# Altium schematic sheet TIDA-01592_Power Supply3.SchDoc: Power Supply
size 431 x 279 mm; Date: Not shown in title block; ApprovedBy: Not shown in title block; CheckedBy: Not shown in title block; Author: Not shown in title block; CompanyName: Not shown in title block; DrawnBy: Abhishek Vishwa; Engineer: Abhishek Vishwa; Organization: Not shown in title block; Address1: Not shown in title block; Address2: Not shown in title block; Address3: Not shown in title block; Address4: Not shown in title block; DocumentNumber: 1; Revision: Use project parameter SCH_Rev; SheetNumber: 4; SheetTotal: 5; PageSetup: Record=PageOptions¦CenterHorizontal=True¦CenterVertical=True¦PrintScale=1.00¦XCorrection=1.00¦YCorrection=1.00¦PrintKind=0¦BorderSize=5000000¦LeftOffset=0¦BottomOffset=0¦Orientation=2¦PaperLength=1000¦PaperWidth=1000¦Scale=100¦PaperSource=15¦PrintQuality=600¦MediaType=1¦DitherType=10¦PaperKind=Letter¦PrintScaleMode=1
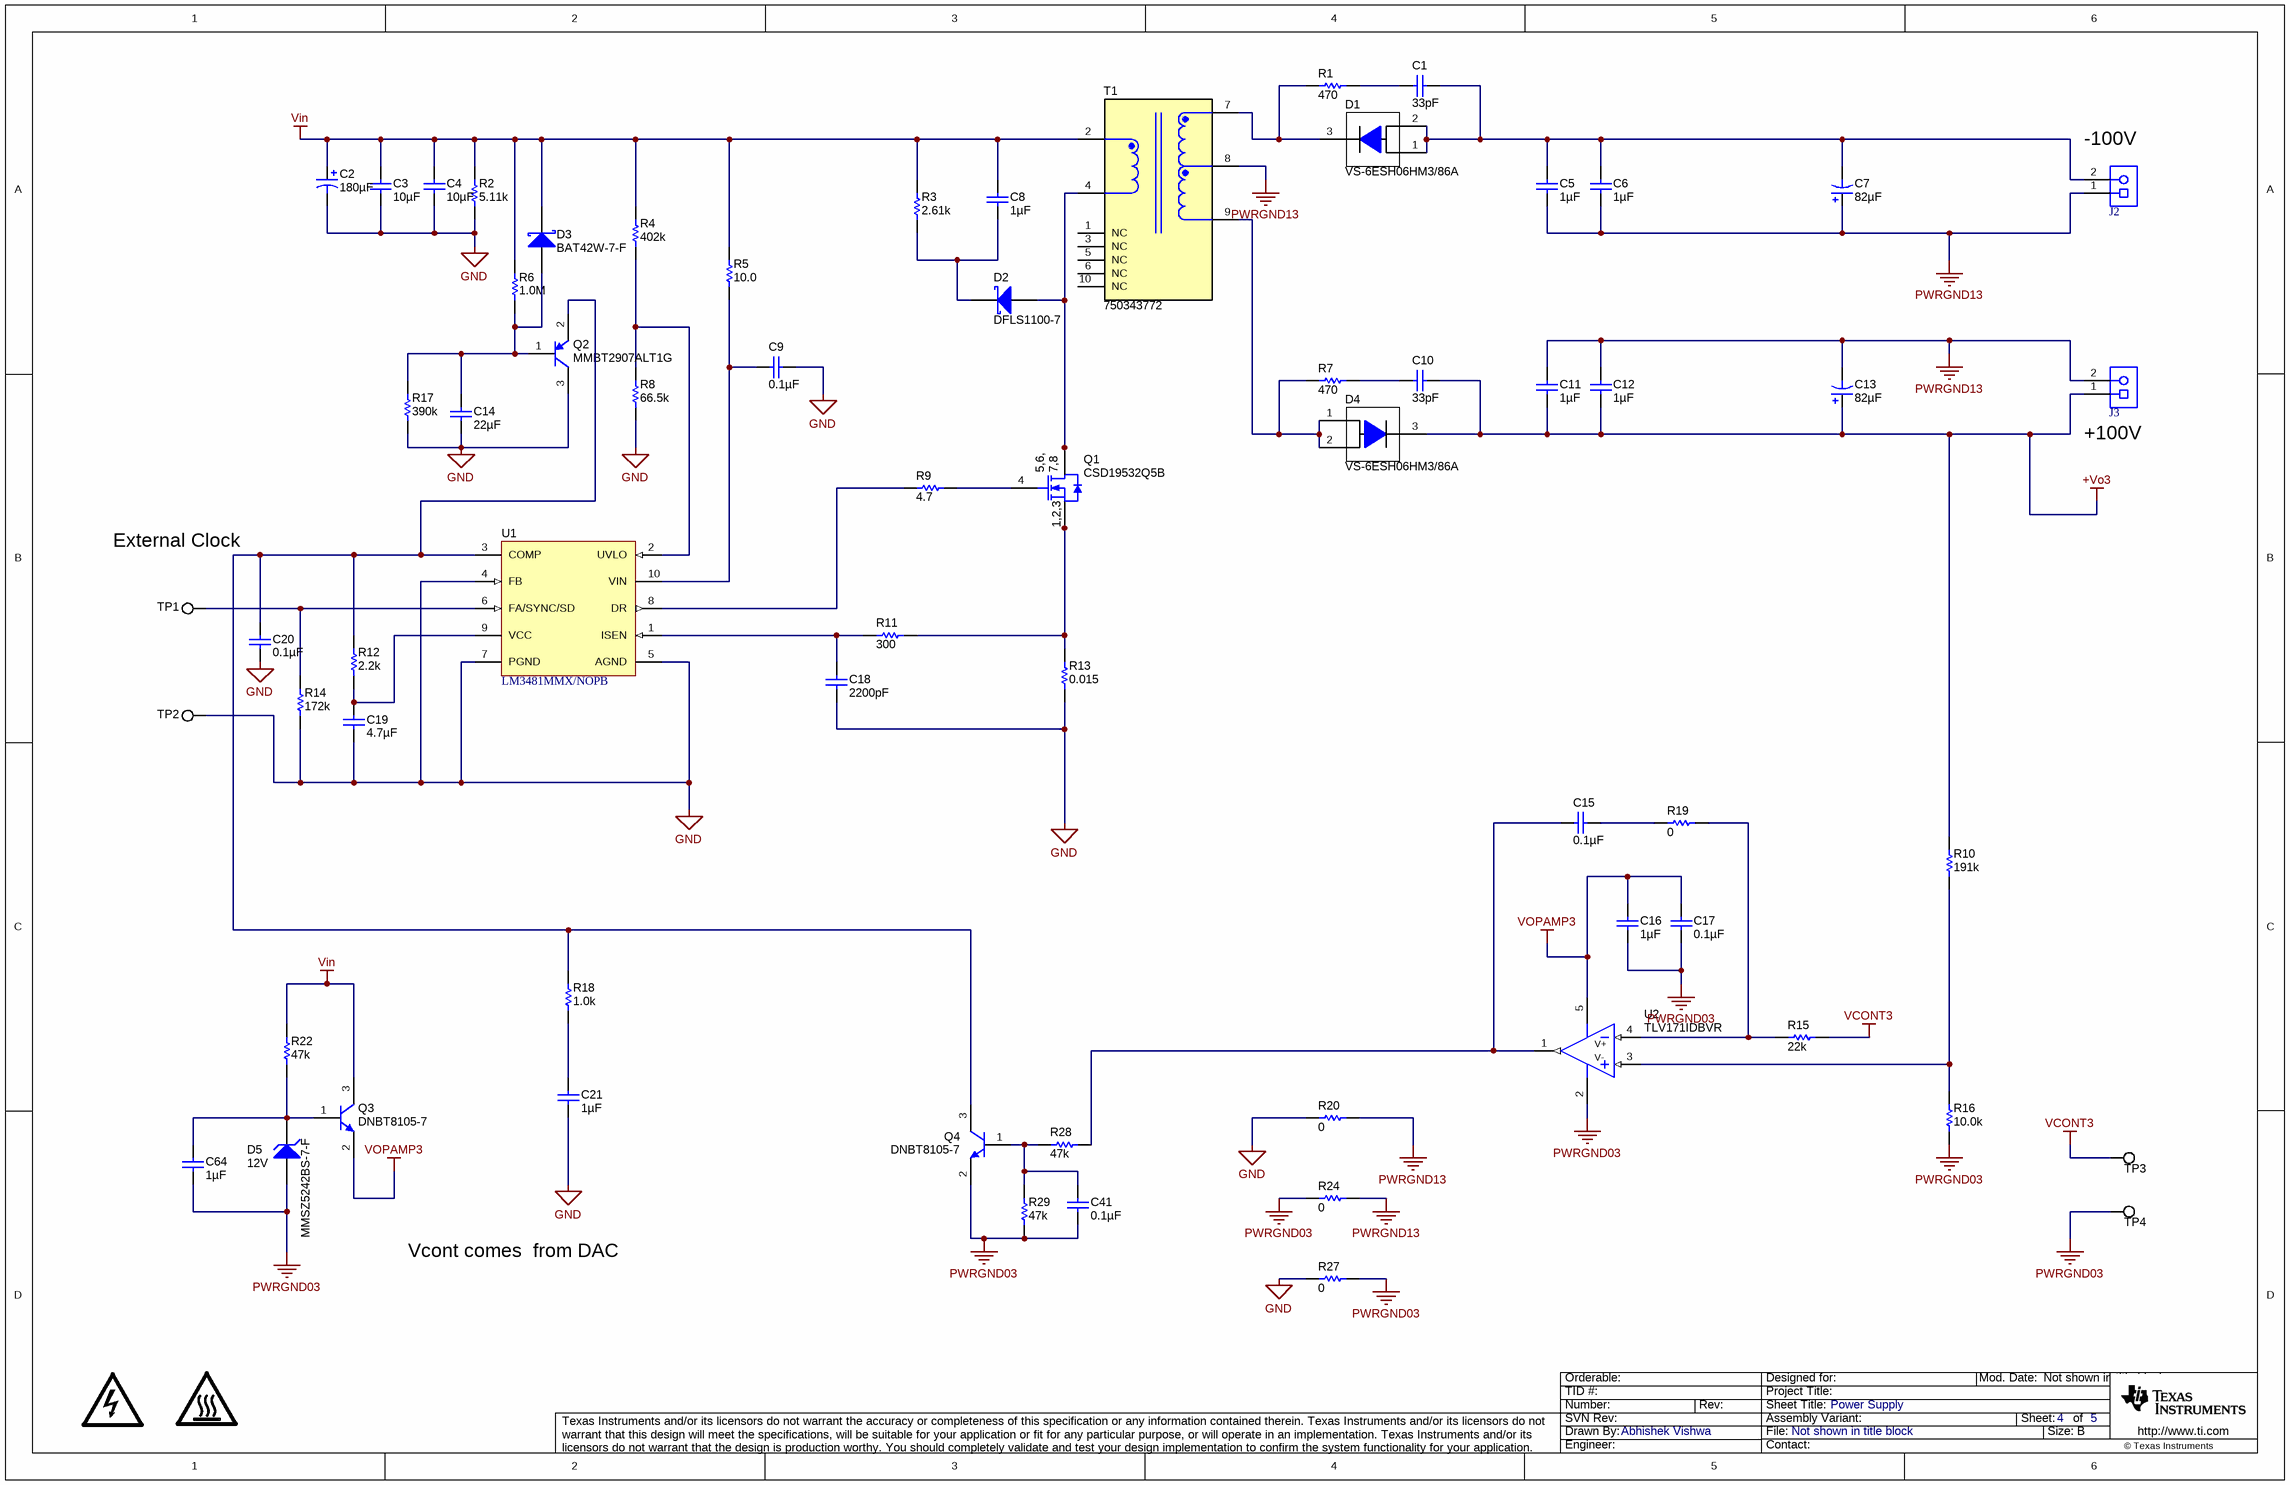
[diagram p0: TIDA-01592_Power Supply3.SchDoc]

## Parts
C1  ValueDisplayed: 33pF  [1206]  (hidden comment: 12067A330JAT2A)
C2  ValueDisplayed: 180µF  [FC_630x1120]  (hidden comment: 35TXW180MEFC6.3X25)
C3  ValueDisplayed: 10µF  [1206_180]  (hidden comment: GRM31CR61H106KA12L)
C4  ValueDisplayed: 10µF  [1206_180]  (hidden comment: GRM31CR61H106KA12L)
C5  ValueDisplayed: 1µF  [1812_180]  (hidden comment: C4532X7T2E105M250KE)
C6  ValueDisplayed: 1µF  [1812_180]  (hidden comment: C4532X7T2E105M250KE)
C7  ValueDisplayed: 82µF  [NHG_1000x2000]  (hidden comment: UCY2C820MPD9)
C8  ValueDisplayed: 1µF  [1206_180]  (hidden comment: GRM31CR72A105KA01L)
C9  ValueDisplayed: 0.1µF  [0603]  (hidden comment: GRM188R71H104KA93D)
C10  ValueDisplayed: 33pF  [1206]  (hidden comment: 12067A330JAT2A)
C11  ValueDisplayed: 1µF  [1812_180]  (hidden comment: C4532X7T2E105M250KE)
C12  ValueDisplayed: 1µF  [1812_180]  (hidden comment: C4532X7T2E105M250KE)
C13  ValueDisplayed: 82µF  [NHG_1000x2000]  (hidden comment: UCY2C820MPD9)
C14  ValueDisplayed: 22µF  [0805_HV1]  (hidden comment: C2012X5R1V226M125AC)
C15  ValueDisplayed: 0.1µF  [0603]  (hidden comment: GRM188R71H104KA93D)
C16  ValueDisplayed: 1µF  [0603]  (hidden comment: UMK107AB7105KA-T)
C17  ValueDisplayed: 0.1µF  [0603]  (hidden comment: GRM188R71H104KA93D)
C18  ValueDisplayed: 2200pF  [0402]  (hidden comment: GRM155R61H222KA01D)
C19  ValueDisplayed: 4.7µF  [0603]  (hidden comment: 0603ZD475KAT2A)
C20  ValueDisplayed: 0.1µF  [0603]  (hidden comment: GRM188R71H104KA93D)
C21  ValueDisplayed: 1µF  [0603]  (hidden comment: C0603C105K3RACTU)
C41  ValueDisplayed: 0.1µF  [0603]  (hidden comment: GRM188R71H104KA93D)
C64  ValueDisplayed: 1µF  [0603]  (hidden comment: C0603C105K3RACTU)
D1  VS-6ESH06HM3/86A  [TO-277A]
D2  DFLS1100-7  [PowerDI123]
D3  BAT42W-7-F  [SOD-123]
D4  VS-6ESH06HM3/86A  [TO-277A]
D5  MMSZ5242BS-7-F  value 12V  [SOD-323]
J2  1727010  [PhoenixConact_1727010]  (value not drawn)
J3  1727010  [PhoenixConact_1727010]  (value not drawn)
LOGO2  CAUTION HOT SURFACE  [IEC_HotSurface_Small]  (value not drawn)  (graphical)
LOGO8  DANGER HIGH VOLTAGE  [IEC_HighVoltage_Small]  (value not drawn)  (graphical)
Q1  CSD19532Q5B  [DNK0008A]
Q2  MMBT2907ALT1G  [SOT-23]
Q3  DNBT8105-7  [SOT-23]
Q4  DNBT8105-7  [SOT-23]
R1  ValueDisplayed: 470  [1206]  (hidden comment: CRCW1206470RJNEA)
R2  ValueDisplayed: 5.11k  [TNPW0603]  (hidden comment: TNPW06035K11BEEA)
R3  ValueDisplayed: 2.61k  [2010]  (hidden comment: CRCW20102K61FKEF)
R4  ValueDisplayed: 402k  [0603]  (hidden comment: CRCW0603402KFKEA)
R5  R4: 10.0  [0603]  (hidden comment: CRCW060310R0FKEAHP)
R6  ValueDisplayed: 1.0M  [0603]  (hidden comment: CRCW06031M00JNEA)
R7  ValueDisplayed: 470  [1206]  (hidden comment: CRCW1206470RJNEA)
R8  ValueDisplayed: 66.5k  [0603]  (hidden comment: CRCW060366K5FKEA)
R9  ValueDisplayed: 4.7  [0603]  (hidden comment: CRCW06034R70JNEA)
R10  ValueDisplayed: 191k  [0603]  (hidden comment: CRCW0603191KFKEA)
R11  ValueDisplayed: 300  [0603]  (hidden comment: CRCW0603300RJNEA)
R12  ValueDisplayed: 2.2k  [0603]  (hidden comment: ERJ-3GEYJ222V)
R13  ValueDisplayed: 0.015  [2010]  (hidden comment: WSL2010R0150FEA18)
R14  ValueDisplayed: 172k  [0603]  (hidden comment: RT0603DRE07172KL)
R15  ValueDisplayed: 22k  [0603]  (hidden comment: CRCW060322K0JNEA)
R16  ValueDisplayed: 10.0k  [0603]  (hidden comment: CRCW060310K0FKEA)
R17  ValueDisplayed: 390k  [0603]  (hidden comment: CRCW0603390KJNEA)
R18  ValueDisplayed: 1.0k  [0603]  (hidden comment: CRCW06031K00JNEA)
R19  ValueDisplayed: 0  [0402]  (hidden comment: CRCW04020000Z0ED)
R20  ValueDisplayed: 0  [2010L]  (hidden comment: CRCW20100000Z0EF)
R22  ValueDisplayed: 47k  [1206]  (hidden comment: CRCW120647K0JNEA)
R24  ValueDisplayed: 0  [2010L]  (hidden comment: CRCW20100000Z0EF)
R27  ValueDisplayed: 0  [2010L]  (hidden comment: CRCW20100000Z0EF)
R28  ValueDisplayed: 47k  [0603]  (hidden comment: RC0603JR-0747KL)
R29  ValueDisplayed: 47k  [0603]  (hidden comment: RC0603JR-0747KL)
T1  750343772  [Wurth_EE16_7_5_5278]
TP1  5002  [Keystone5002]  (value not drawn)
TP2  5002  [Keystone5002]  (value not drawn)
TP3  5002  [Keystone5002]  (value not drawn)
TP4  5002  [Keystone5002]  (value not drawn)
U1  LM3481MMX/NOPB  [MUB10A_N]
U2  TLV171IDBVR  [DBV0005A_N]

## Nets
+Vo3: C10.1 C11.2 C12.2 C13.1(+) D4.3(K) J3.1 R10.2
GND: C2.2(-) C3.2 C4.2 C9.1 C14.2 C18.2 C19.2 C20.1 C21.2 Q2.3(C) R2.1 R8.1 R13.1 R14.1 R17.1 R20.1 R27.1 TP2.1 U1.4(FB) U1.5(AGND) U1.7(PGND)
PWRGND03: C16.2 C17.2 C41.1 C64.2 D5.2(A) Q4.2(E) R16.2 R24.1 R27.2 R29.2 TP4.1 U2.2(V-)
PWRGND13: C5.2 C6.2 C7.1(+) C11.1 C12.1 C13.2(-) J2.1 J3.2 R20.2 R24.2 T1.8
VCONT3: R15.2 TP3.1
Vin: C2.1(+) C3.1 C4.1 C8.1 D3.1(K) Q3.3(C) R2.2 R3.2 R4.2 R5.1 R6.2 R22.2 T1.2
VOPAMP3: C16.1 C17.1 Q3.2(E) U2.5(V+)
NetC1_1: C1.1 C5.1 C6.1 C7.2(-) D1.1(A) D1.2(A) J2.2
NetC1_2: C1.2 R1.2
NetC8_2: C8.2 D2.1(K) R3.1
NetC9_2: C9.2 R5.2 U1.10(VIN)
NetC10_2: C10.2 R7.2
NetC14_1: C14.1 D3.2(A) Q2.1(B) R6.1 R17.2
NetC15_1: C15.1 R28.1 U2.1(OUT)
NetC15_2: C15.2 R19.1
NetC18_1: C18.1 R11.1 U1.1(ISEN)
NetC19_1: C19.1 R12.2 U1.9(VCC)
NetC20_2: C20.2 Q2.2(E) Q4.3(C) R12.1 R18.2 U1.3(COMP)
NetC21_1: C21.1 R18.1
NetC41_2: C41.2 Q4.1(B) R28.2 R29.1
NetC64_1: C64.1 D5.1(K) Q3.1(B) R22.1
NetD1_3: D1.3(K) R1.1 T1.7
NetD2_2: D2.2(A) Q1.5(D) Q1.6(D) Q1.7(D) Q1.8(D) Q1.9(D) T1.4
NetD4_1: D4.1(A) D4.2(A) R7.1 T1.9
NetQ1_1: Q1.1(S) Q1.2(S) Q1.3(S) R11.2 R13.2
NetQ1_4: Q1.4(G) R9.2
NetR4_1: R4.1 R8.2 U1.2(UVLO)
NetR9_1: R9.1 U1.8(DR)
NetR10_1: R10.1 R16.1 U2.3(IN+)
NetR14_2: R14.2 TP1.1 U1.6(FA/SYNC/SD)
NetR15_1: R15.1 R19.2 U2.4(IN-)

Not connected (* = marked no-connect by the designer): T1 1(NC) 3(NC) 5(NC) 6(NC) 10(NC)

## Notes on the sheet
- (near J2) -100V
- (near J3) +100V
- External Clock Synchronization
- Vcont comes  from DAC

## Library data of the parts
C1 C10 = 12067A330JAT2A: CAP, CERM, 33 pF, 500 V,+/- 5%, C0G/NP0, 1206; Manufacturer: AVX; Polarized: N; CompType: Capacitor; Value: 33pF; U/M: EA; Cap_F: 0.000000000033; Tolerance_%: 5; VDC_V: 500; Value2: 500V; TaMin_C: -55; TaMax_C: 125; SizeArea_mm2: 5.12; SizeAreaWB_mm2: 10.92; SizeX_mm: 3.2; SizeY_mm: 1.6; SizeZ_mm: 1.35; AEC Category: Q200; Green_Lifecycle: Not Set; Green_REACh: Incomplete
C2 = EEU-FC1V470: CAP, AL, 180 µF, 35 V, +/- 20%, TH; Manufacturer: Rubycon; Polarized: Y; CompType: Capacitor; Value: 180uF; U/M: EA; Cap_F: 0.000180; Tolerance_%: 20; VDC_V: 35; Value2: 35V; IRMS_A: 0.29; TaMin_C: -55; TaMax_C: 105; Cap_Case: 6.3x11.2mm; SizeAreaWB_mm2: 68.89; SizeArea_mm2: 39.69; SizeX_mm: 6.3; SizeZ_mm: 12.2; AEC Category: Q200; AEC Grade: 2
C3 C4 = GRM31CR61H106KA12L: CAP, CERM, 10 µF, 50 V,+/- 10%, X5R, 1206; Manufacturer: MuRata; Polarized: N; CompType: Capacitor; Value: 10uF; U/M: EA; Cap_F: 0.00001; Tolerance_%: 10; VDC_V: 50; Value2: 50V; TaMin_C: -55; TaMax_C: 85; Cap_Case: 1206; SizeArea_mm2: 5.12; SizeAreaWB_mm2: 10.92; SizeX_mm: 3.2; SizeY_mm: 1.6; SizeZ_mm: 1.8; AEC Category: Q200; Green_Lifecycle: Active; Green_REACh: Passed
C5 C6 C11 C12 = C4532X7R1H105K160KA: CAP, CERM, 1 µF, 250 V,+/- 20%, X7T, 1812; Manufacturer: TDK Corporation; Polarized: N; CompType: Capacitor; Value: 1uF; U/M: EA; Cap_F: 0.000001; Tolerance_%: 20; ESR_ohm: 0.007217; Value1: 0.007217 ohm; VDC_V: 50; Value2: 250V; IRMS_A: 2.85919; TaMin_C: -55; TaMax_C: 125; Cap_Case: 1812; SizeArea_mm2: 14.4; SizeAreaWB_mm2: 23.1; SizeX_mm: 4.5; SizeY_mm: 3.2; SizeZ_mm: 1.8; AEC Category: Q200
C7 C13 = ECA-2AHG101: CAP, AL, 82 µF, 160 V, +/- 20%, TH; Manufacturer: Nichicon; Polarized: Y; CompType: Capacitor; Value: 82uF; U/M: EA; Cap_F: 0.0001; Tolerance_%: 20; VDC_V: 160; Value2: 160V; IRMS_A: 0.265; TaMin_C: -55; TaMax_C: 105; Cap_Case: 10x20mm; SizeAreaWB_mm2: 144; SizeArea_mm2: 100; SizeX_mm: 10; SizeZ_mm: 22; AEC Category: Q200; Green_Lifecycle: Active; Green_REACh: Passed
C8 = GRM31CR72A105KA01L: CAP, CERM, 1 µF, 100 V,+/- 10%, X7R, 1206; Manufacturer: MuRata; Polarized: N; CompType: Capacitor; Value: 1uF; U/M: EA; Cap_F: 0.000001; Tolerance_%: 10; VDC_V: 100; Value2: 100V; TaMin_C: -55; TaMax_C: 125; Cap_Case: 1206; SizeArea_mm2: 5.12; SizeAreaWB_mm2: 10.92; SizeX_mm: 3.2; SizeY_mm: 1.6; SizeZ_mm: 1.8; AEC Category: Q200; Green_Lifecycle: Active; Green_REACh: Passed
C9 C15 C17 C20 C41 = GRM188R71H104KA93D: CAP, CERM, 0.1 µF, 50 V,+/- 10%, X7R, 0603; Manufacturer: MuRata; Polarized: N; CompType: Capacitor; Value: 0.1uF; U/M: EA; Cap_F: 0.0000001; Tolerance_%: 10; VDC_V: 50; Value2: 50V; TaMin_C: -55; TaMax_C: 125; SizeArea_mm2: 1.28; SizeAreaWB_mm2: 4.68; SizeX_mm: 1.6; SizeY_mm: 0.8; SizeZ_mm: 1; AEC Category: Q200; Green_Lifecycle: Active; Green_REACh: Passed
C14 = GRM21BC81C226ME44L: CAP, CERM, 22 µF, 35 V,+/- 20%, X5R, 0805; Manufacturer: TDK Corporation; Polarized: N; CompType: Capacitor; Value: 22uF; U/M: EA; Cap_F: 0.000022; Tolerance_%: 20; VDC_V: 16; Value2: 35V; TempCo: X6S; TaMin_C: -55; TaMax_C: 105; Cap_Case: 0805; SizeArea_mm2: 2.5; SizeAreaWB_mm2: 6.75; SizeX_mm: 2; SizeY_mm: 1.25; SizeZ_mm: 1.45; AEC Category: Q200
C16 = UMK107AB7105KA-T: CAP, CERM, 1 µF, 50 V,+/- 10%, X7R, 0603; Manufacturer: Taiyo Yuden; Polarized: N; CompType: Capacitor; Value: 1uF; U/M: EA; Cap_F: 0.000001; Tolerance_%: 10; VDC_V: 50; Value2: 50V; TaMin_C: -55; TaMax_C: 125; SizeArea_mm2: 1.28; SizeAreaWB_mm2: 4.68; SizeX_mm: 1.6; SizeY_mm: 0.8; SizeZ_mm: 1; AEC Category: Q200; Green_Lifecycle: Active; Green_REACh: Passed
C18 = GRM155R61H222KA01D: CAP, CERM, 2200 pF, 50 V,+/- 10%, X5R, 0402; Manufacturer: MuRata; Polarized: N; CompType: Capacitor; Value: 2200pF; U/M: EA; Cap_F: 0.0000000022; Tolerance_%: 10; VDC_V: 50; Value2: 50V; TaMin_C: -55; TaMax_C: 85; SizeArea_mm2: 0.5; SizeAreaWB_mm2: 3; SizeX_mm: 1; SizeZ_mm: 0.6; AEC Category: Q200; Green_Lifecycle: Active; Green_REACh: Passed
C19 = 0603ZD475KAT2A: CAP, CERM, 4.7 µF, 10 V,+/- 10%, X5R, 0603; Manufacturer: AVX; Polarized: N; CompType: Capacitor; Value: 4.7uF; U/M: EA; Cap_F: 0.0000047; Tolerance_%: 10; Value2: 10V; TaMin_C: -55; TaMax_C: 85; SizeArea_mm2: 1.28; SizeAreaWB_mm2: 4.68; SizeX_mm: 1.6; SizeY_mm: 0.8; SizeZ_mm: 1; AEC Category: Q200; Green_Lifecycle: Active; Green_REACh: Passed
C21 C64 = C0603C105K3RACTU: CAP, CERM, 1 µF, 25 V,+/- 10%, X7R, 0603; Manufacturer: Kemet; Polarized: N; CompType: Capacitor; Value: 1uF; U/M: EA; Cap_F: 0.000001; Tolerance_%: 10; VDC_V: 25; Value2: 25V; TaMin_C: -55; TaMax_C: 125; SizeArea_mm2: 1.28; SizeAreaWB_mm2: 4.68; SizeX_mm: 1.6; SizeY_mm: 0.8; SizeZ_mm: 1; AEC Category: Q200; Green_Lifecycle: Active; Green_REACh: Passed
D1 D4 = VS-6ESH06HM3/86A: Diode, Hyperfast, 600 V, 6 A, AEC-Q101, TO-277A; Manufacturer: Vishay-Semiconductor; SymbolCreator: a0412235; U/M: EA; Vf_V: 1.05; Value: 600V; Value1: 6A; Value2: 1.05V; Io_A: 6; Vr_V: 600; TJmax_C: 175; RJC_CperW: 3.5; SizeAreaWB_mm2: 57.375; SizeArea_mm2: 30.875; SizeX_mm: 6.5; SizeY_mm: 4.75; SizeZ_mm: 1.2; AEC Category: Q101; AEC Qualified: Y
D2 = DFLS1100-7: Diode, Schottky, 100 V, 1 A, PowerDI123; Manufacturer: Diodes Inc.; U/M: EA; Vf_V: 0.77; Value: 100V; Value1: 1A; Value2: 0.77V; Io_A: 1; Vr_V: 100; TJmax_C: 175; RJC_CperW: 7; SizeAreaWB_mm2: 13.066; SizeArea_mm2: 6.586; SizeX_mm: 3.7; SizeY_mm: 1.78; SizeZ_mm: 0.98; AEC Category: Q101; Green_Lifecycle: Active; Green_REACh: Passed
D3 = BAT42W-7-F: Diode, Schottky, 30 V, 0.2 A, SOD-123; Manufacturer: Diodes Inc.; U/M: EA; Vf_V: 1; Value: 30V; Value1: 0.2A; Value2: 1V; Io_A: 0.2; Vr_V: 30; SizeAreaWB_mm2: 13.095; SizeArea_mm2: 6.545; SizeX_mm: 3.85; SizeY_mm: 1.7; SizeZ_mm: 1.35; AEC Category: Q101; Green_Lifecycle: Not Set; Green_REACh: Incomplete
D5 = MMSZ5242BS-7-F: Diode, Zener, 12 V, 200 mW, SOD-323; Manufacturer: Diodes Inc.; SymbolCreator: a0412235; U/M: EA; Power_W: 0.2; Vz_V: 12; Value1: 0.2W; RJA_CperW: 350; SizeAreaWB_mm2: 8.695; SizeArea_mm2: 3.645; SizeX_mm: 2.7; SizeY_mm: 1.35; SizeZ_mm: 1; AEC Category: Q101
J2 J3 = 1727010: Conn Term Block, 2POS, 3.81mm, TH; Manufacturer: Phoenix Contact; SymbolCreator: a0412235; CompType: Terminal Block
LOGO2 = IEC_HotSurface: IEC 61010-1 Hot Surface Warning; SymbolCreator: a0412235
LOGO8 = IEC_HighVoltage: IEC 61010-1 High Voltage Warning; SymbolCreator: a0412235
Q1 = CSD19532Q5B: MOSFET, N-CH, 100 V, 17 A, DNK0008A (VSON-CLIP-8); Manufacturer: Texas Instruments; Alternate Manufacturer: None; U/M: EA; ChType: N; Value: 100V; VdsMax_V: 100; Value1: ? ohm; Value2: 48 nC; QgTyp_nC: 48; Vgs_V: 20; IdsMax_A: 17; SizeAreaWB_mm2: 56; SizeArea_mm2: 30; SizeX_mm: 6; SizeY_mm: 5; SizeZ_mm: 1; AEC Category: Q101
Q2 = MMBT2907ALT1G, ON Semiconductor: Transistor, PNP, 60 V, 0.6 A, SOT-23; CompType: BJT; PNP: 1; NPN: 0; Vceo_V: 60; Vcesat1_V: 1.6; Value: 60 V; IcRated_A: 0.6; Value1: 0.6 A; TaMin_C: -55; TaMax_C: 150; SizeAreaWB_mm2: 14; SizeArea_mm2: 7.5; SizeX_mm: 2.5; SizeY_mm: 3; SizeZ_mm: 1.1; U/M: EA; AEC Category: Q101; Green_Lifecycle: Active; Green_REACh: Passed
Q3 Q4 = DNBT8105-7, Diodes Inc.: Transistor, NPN, 60 V, 1 A, AEC-Q101, SOT-23; CompType: BJT; PNP: 0; NPN: 1; Vceo_V: 60; Vcesat1_V: 0.25; Value: 60 V; Value1: 1 A; HfeMax: 300; TaMin_C: -55; TaMax_C: 150; SizeAreaWB_mm2: 14; SizeArea_mm2: 7.5; SizeX_mm: 2.5; SizeY_mm: 3; SizeZ_mm: 1.1; U/M: EA; AEC Category: Q101; AEC Qualified: Y; Green_Lifecycle: Not Set; Green_REACh: Incomplete
R1 R7 = CRCW1206470RJNEA: RES, 470, 5%, 0.25 W, 1206; Manufacturer: Vishay-Dale; CompType: Resistor; Value: 470; Value_Code: 470R; Tolerance_%: 5; Power_W: 0.25; Value2: 0.25W; VDC_V: 200; TempCo: 200 ppm/C; SizeArea_mm2: 5.12; SizeX_mm: 3.2; SizeY_mm: 1.6; SizeZ_mm: 1.35; EIA_Code: E24; U/M: EA; AEC Category: Q200
R2 = TNPW06035K11BEEA: RES, 5.11 k, 0.1%, 0.1 W, AEC-Q200 Grade 1, 0603; Manufacturer: Vishay-Dale; CompType: Resistor; Value: 5.11k; Res_ohm: 5110; Value_Code: 5k11; Tolerance_%: 0.1; Value2: 0.1W; VDC_V: 75; TempCo: 25 ppm/C; SizeArea_mm2: 1.36; SizeX_mm: 1.6; SizeY_mm: 0.85; SizeZ_mm: 0.55; EIA_Code: E192; U/M: EA; AEC Category: Q200; AEC Qualified: Y; AEC Grade: 1
R3 = CRCW20102K61FKEF: RES, 2.61 k, 1%, 0.75 W, AEC-Q200 Grade 0, 2010; Manufacturer: Vishay-Dale; CompType: Resistor; Value: 2.61k; Res_ohm: 2610; Value_Code: 2k61; Tolerance_%: 1; Power_W: 0.75; Value2: 0.75W; VDC_V: 400; TempCo: 100 ppm/C; SizeArea_mm2: 12.5; SizeX_mm: 5; SizeY_mm: 2.5; SizeZ_mm: 1.66; EIA_Code: E96; U/M: EA; AEC Category: Q200; AEC Qualified: Y; AEC Grade: 0
R4 = CRCW0603402KFKEA: RES, 402 k, 1%, 0.1 W, 0603; Manufacturer: Vishay-Dale; CompType: Resistor; Value: 402k; Res_ohm: 402000; Tolerance_%: 1; Power_W: 0.1; Value2: 0.1W; VDC_V: 75; TempCo: 100 ppm/C; SizeArea_mm2: 1.28; SizeX_mm: 1.6; SizeY_mm: 0.8; EIA_Code: E96; U/M: EA; AEC Category: Q200; Green_Lifecycle: Active; Green_REACh: Passed
R5 = CRCW060310R0FKEAHP: RES, 10.0, 1%, 0.25 W, 0603; Manufacturer: Vishay-Dale; CompType: Resistor; Value: 10.0; Res_ohm: 10; Value_Code: 10R0; Tolerance_%: 1; Power_W: 0.25; Value2: 0.25W; VDC_V: 75; TempCo: 100 ppm/C; SizeArea_mm2: 1.28; SizeX_mm: 1.6; SizeY_mm: 0.8; EIA_Code: E96; U/M: EA; AEC Category: Q200; Green_Lifecycle: Active; Green_REACh: Passed
R6 = CRCW06031M00JNEA: RES, 1.0 M, 5%, 0.1 W, 0603; Manufacturer: Vishay-Dale; CompType: Resistor; Value: 1.0Meg; Res_ohm: 1000000; Value_Code: 1M00; Tolerance_%: 5; Power_W: 0.1; Value2: 0.1W; VDC_V: 75; TempCo: 200 ppm/C; SizeArea_mm2: 1.28; SizeX_mm: 1.6; SizeY_mm: 0.8; SizeZ_mm: 1; EIA_Code: E24; U/M: EA; AEC Category: Q200; Green_Lifecycle: Active; Green_REACh: Passed
R8 = CRCW060366K5FKEA: RES, 66.5 k, 1%, 0.1 W, 0603; Manufacturer: Vishay-Dale; CompType: Resistor; Value: 66.5k; Res_ohm: 66500; Value_Code: 66k5; Tolerance_%: 1; Power_W: 0.1; Value2: 0.1W; VDC_V: 75; TempCo: 100 ppm/C; SizeArea_mm2: 1.28; SizeX_mm: 1.6; SizeY_mm: 0.8; EIA_Code: E96; U/M: EA; AEC Category: Q200; Green_Lifecycle: Active; Green_REACh: Passed
R9 = CRCW06034R70JNEA: RES, 4.7, 5%, 0.1 W, 0603; Manufacturer: Vishay-Dale; CompType: Resistor; Value: 4.7; Value_Code: 4R70; Tolerance_%: 5; Power_W: 0.1; Value2: 0.1W; VDC_V: 75; TempCo: 200 ppm/C; SizeArea_mm2: 1.28; SizeX_mm: 1.6; SizeY_mm: 0.8; SizeZ_mm: 1; EIA_Code: E24; U/M: EA; AEC Category: Q200; Green_Lifecycle: Active; Green_REACh: Passed
R10 = CRCW0603191KFKEA: RES, 191 k, 1%, 0.1 W, 0603; Manufacturer: Vishay-Dale; CompType: Resistor; Value: 191k; Res_ohm: 191000; Tolerance_%: 1; Power_W: 0.1; Value2: 0.1W; VDC_V: 75; TempCo: 100 ppm/C; SizeArea_mm2: 1.28; SizeX_mm: 1.6; SizeY_mm: 0.8; EIA_Code: E96; U/M: EA; AEC Category: Q200; Green_Lifecycle: Active; Green_REACh: Passed
R11 = CRCW0603300RJNEA: RES, 300, 5%, 0.1 W, 0603; Manufacturer: Vishay-Dale; CompType: Resistor; Value: 300; Value_Code: 300R; Tolerance_%: 5; Power_W: 0.1; Value2: 0.1W; VDC_V: 75; TempCo: 200 ppm/C; SizeArea_mm2: 1.28; SizeX_mm: 1.6; SizeY_mm: 0.8; SizeZ_mm: 1; EIA_Code: E24; U/M: EA; AEC Category: Q200; Green_Lifecycle: Active; Green_REACh: Passed
R12 = ERJ-3GEYJ222V: RES, 2.2 k, 5%, 0.1 W, AEC-Q200 Grade 0, 0603; Manufacturer: Panasonic; CompType: Resistor; Value: 2.2k; Res_ohm: 2200; Value_Code: 2k20; Tolerance_%: 5; Power_W: 0.1; Value2: 0.1W; VDC_V: 75; TempCo: 200 ppm/C; SizeArea_mm2: 1.28; SizeX_mm: 1.6; SizeY_mm: 0.8; SizeZ_mm: 1; EIA_Code: E24; U/M: EA; AEC Category: Q200; AEC Qualified: Y; AEC Grade: 0; Green_Lifecycle: Active; Green_REACh: Passed
R13 = WSL2010R0150FEA18: RES, 0.015, 1%, 1 W, 2010; Manufacturer: Vishay-Dale; CompType: Resistor; Value: 0.015; Value_Code: R015; Tolerance_%: 1; Value2: 1W; TempCo: 75 ppm/C; SizeArea_mm2: 12.5; SizeX_mm: 5; SizeY_mm: 2.5; SizeZ_mm: 1.66; EIA_Code: E96; U/M: EA; AEC Category: Q200
R14 = RT0603DRE07172KL: RES, 172 k, 0.5%, 0.1 W, 0603; Manufacturer: Yageo America; CompType: Resistor; Value: 172k; Res_ohm: 172000; Tolerance_%: 0.5; Power_W: 0.1; Value2: 0.1W; VDC_V: 75; TempCo: 50 ppm/C; SizeArea_mm2: 1.28; SizeX_mm: 1.6; SizeY_mm: 0.8; SizeZ_mm: 1; EIA_Code: E192; U/M: EA; AEC Category: Q200
R15 = CRCW060322K0JNEA: RES, 22 k, 5%, 0.1 W, 0603; Manufacturer: Vishay-Dale; CompType: Resistor; Value: 22k; Res_ohm: 22000; Value_Code: 22k0; Tolerance_%: 5; Power_W: 0.1; Value2: 0.1W; VDC_V: 75; TempCo: 200 ppm/C; SizeArea_mm2: 1.28; SizeX_mm: 1.6; SizeY_mm: 0.8; SizeZ_mm: 1; EIA_Code: E24; U/M: EA; AEC Category: Q200; Green_Lifecycle: Active; Green_REACh: Passed
R16 = CRCW060310K0FKEA: RES, 10.0 k, 1%, 0.1 W, 0603; Manufacturer: Vishay-Dale; CompType: Resistor; Value: 10.0k; Res_ohm: 10000; Value_Code: 10k0; Tolerance_%: 1; Power_W: 0.1; Value2: 0.1W; VDC_V: 75; TempCo: 100 ppm/C; SizeArea_mm2: 1.28; SizeX_mm: 1.6; SizeY_mm: 0.8; EIA_Code: E96; U/M: EA; AEC Category: Q200; Green_Lifecycle: Active; Green_REACh: Passed
R17 = CRCW0603390KJNEA: RES, 390 k, 5%, 0.1 W, 0603; Manufacturer: Vishay-Dale; CompType: Resistor; Value: 390k; Res_ohm: 390000; Tolerance_%: 5; Power_W: 0.1; Value2: 0.1W; VDC_V: 75; TempCo: 200 ppm/C; SizeArea_mm2: 1.28; SizeX_mm: 1.6; SizeY_mm: 0.8; SizeZ_mm: 1; EIA_Code: E24; U/M: EA; AEC Category: Q200
R18 = CRCW06031K00JNEA: RES, 1.0 k, 5%, 0.1 W, 0603; Manufacturer: Vishay-Dale; CompType: Resistor; Value: 1.0k; Res_ohm: 1000; Value_Code: 1k00; Tolerance_%: 5; Power_W: 0.1; Value2: 0.1W; VDC_V: 75; TempCo: 200 ppm/C; SizeArea_mm2: 1.28; SizeX_mm: 1.6; SizeY_mm: 0.8; SizeZ_mm: 1; EIA_Code: E24; U/M: EA; AEC Category: Q200; Green_Lifecycle: Active; Green_REACh: Passed
R19 = CRCW04020000Z0ED: RES, 0, 5%, 0.063 W, 0402; Manufacturer: Vishay-Dale; CompType: Resistor; Value: 0; Value_Code: 0000; Tolerance_%: 5; Power_W: 0.063; Value2: 0.063W; VDC_V: 50; TempCo: 200 ppm/C; SizeArea_mm2: 0.5; SizeX_mm: 1; SizeZ_mm: 0.6; EIA_Code: E24; U/M: EA; AEC Category: Q200; Green_Lifecycle: Active; Green_REACh: Passed
R20 R24 R27 = CRCW20100000Z0EF: RES, 0, 5%, 0.75 W, AEC-Q200 Grade 0, 2010; Manufacturer: Vishay-Dale; CompType: Resistor; Value: 0; Value_Code: 0000; Tolerance_%: 5; Power_W: 0.75; Value2: 0.75W; TempCo: ppm/C; SizeArea_mm2: 12.5; SizeY_mm: 2.5; SizeZ_mm: 1.66; EIA_Code: E24; U/M: EA; AEC Category: Q200; AEC Qualified: Y
R22 = CRCW120647K0JNEA: RES, 47 k, 5%, 0.25 W, 1206; Manufacturer: Vishay-Dale; CompType: Resistor; Value: 47k; Res_ohm: 47000; Value_Code: 47k0; Tolerance_%: 5; Power_W: 0.25; Value2: 0.25W; VDC_V: 200; TempCo: 200 ppm/C; SizeArea_mm2: 5.12; SizeX_mm: 3.2; SizeY_mm: 1.6; SizeZ_mm: 1.35; EIA_Code: E24; U/M: EA; AEC Category: Q200
R28 R29 = RC0603JR-0747KL: RES, 47 k, 5%, 0.1 W, 0603; Manufacturer: Yageo America; CompType: Resistor; Value: 47k; Res_ohm: 47000; Value_Code: 47k0; Tolerance_%: 5; Power_W: 0.1; Value2: 0.1W; VDC_V: 50; TempCo: 100 ppm/C; SizeArea_mm2: 1.28; SizeX_mm: 1.6; SizeY_mm: 0.8; SizeZ_mm: 1; EIA_Code: E24; U/M: EA; AEC Category: Q200; Green_Lifecycle: Active; Green_REACh: Passed
T1 = CMP-0081056-1: Transformer, 13 uH, TH; Manufacturer: Wurth Elektronik; LeakageInd_H: 300nH; Rsec2_ohm: 1.45; SizeAreaWB_mm2: 379.25; DCR_ohm: 0.022; Value: 13uH; Lp: 13; SizeZ_mm: 18.8; SizeX_mm: 16.5; SizeY_mm: 18.5; Ns1toNp: 5.5; SizeArea_mm2: 305.25; Ind_H: 13µH; AEC Qualified: N; Rsec1_ohm: 1; AEC Category: Q200
TP1-TP4 = 5002: Test Point, Miniature, White, TH; Manufacturer: Keystone; CompType: Test Point Loop; ContactFinish: Silver
U1 = LM3481MMX/NOPB: High Efficiency Low-Side N-Channel Controller for Switching Regulators, 10-pin MSOP, Pb-Free; Manufacturer: Texas Instruments; PackageTopMarking: ZXTT*SJPB; PowerWise: N; CompType: MiscPower
U2 = TLV171IDBVR: 36V, Low-Power, RRO, General-Purpose Operational Amplifier, DBV0005A (SOT-23-5); Alternate PartNumber: TLV171IDBVT; Manufacturer: Texas Instruments; SizeArea_mm2: 8.12; SizeAreaWB_mm2: 14.82; SizeX_mm: 2.8; SizeY_mm: 2.9; SizeZ_mm: 1.45; CompType: IC; U/M: EA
